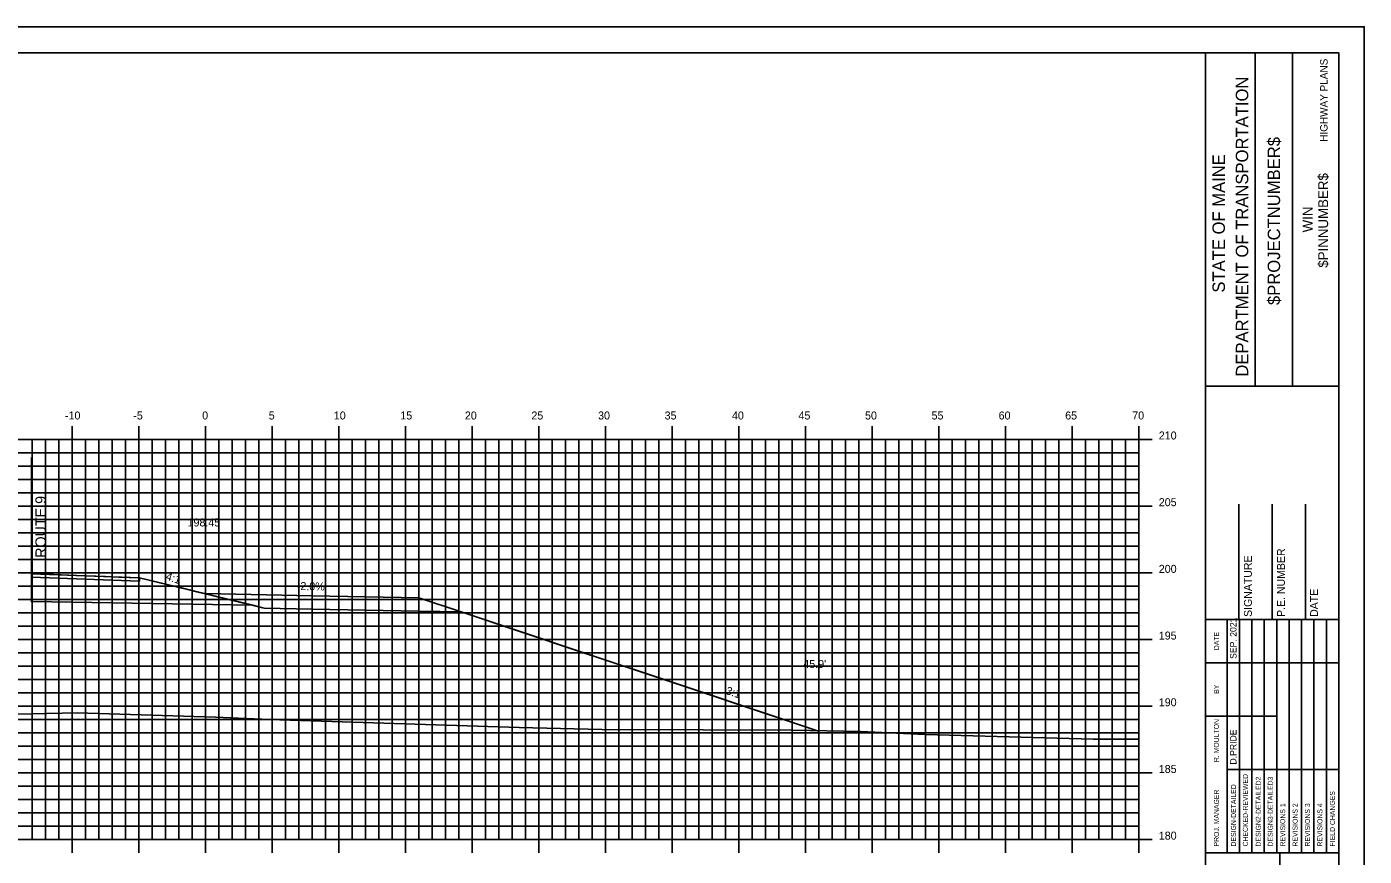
# Model space of a CAD drawing. Extents: x 1723296 to 1723468, y 459560 to 459670.
# Drawn here: x 1723365.8 to 1723466.1, y 459607.4 to 459669.6 of the extents above; entities that cross this region are included whole.
import ezdxf

# ---------------------------------------------------------------- set-up
doc = ezdxf.new("R2010")
doc.units = 0
for name, color, linetype in [('ANNOTATION', 7, 'Continuous'), ('BORDER', 7, 'Continuous'), ('D_Roadway_Centerline', 7, 'Continuous'), ('D_Roadway_Centerline_Text', 7, 'Continuous'), ('D_Roadway_Drive_Gravel', 7, 'Continuous'), ('D_Roadway_Edge_Shoulder', 7, 'Continuous'), ('D_Roadway_Edge_TW', 7, 'Continuous'), ('D_Roadway_Pavement', 7, 'Continuous'), ('D_Roadway_SlopeLines', 7, 'Continuous'), ('D_Roadway_SubGrade', 7, 'Continuous'), ('D_Text_Standard', 7, 'Continuous'), ('H_V ANNOTATION', 7, 'Continuous'), ('HIGHWAY_TITLE', 7, 'Continuous'), ('MAJOR', 7, 'Continuous'), ('MINOR', 7, 'Continuous'), ('PLOT BOUNDARY', 7, 'Continuous'), ('S_Roadway_Centerline', 7, 'Continuous')]:
    doc.layers.add(name, color=color, linetype=linetype)

msp = doc.modelspace()

# ---------------------------------------------------------------- linework, layer by layer
msp.add_lwpolyline([(1723379.2, 459627.06), (1723387.2, 459626.9), (1723395.2, 459626.74), (1723398.39, 459625.68), (1723407.19, 459622.75), (1723411.66, 459621.26), (1723416.09, 459619.78), (1723425.1, 459616.78), (1723425.12, 459616.77), (1723425.16, 459616.76), (1723425.17, 459616.75), (1723425.22, 459616.74)])
at = {"layer": 'BORDER'}
for p, q in [((1723454.2, 459562.61), (1723454.2, 459667.61)), ((1723457.93, 459642.61), (1723457.93, 459667.61)), ((1723460.73, 459642.61), (1723460.73, 459667.61)), ((1723454.2, 459642.61), (1723464.2, 459642.61)), ((1723456.7, 459625.12), (1723456.7, 459633.76)), ((1723459.2, 459625.12), (1723459.2, 459633.76)), ((1723461.7, 459625.12), (1723461.7, 459633.76)), ((1723454.2, 459625.12), (1723464.2, 459625.12)), ((1723454.2, 459607.62), (1723464.2, 459607.62)), ((1723459.79, 459572.62), (1723459.79, 459607.62))]:
    msp.add_line(p, q, dxfattribs=at)
msp.add_lwpolyline([(1723304.2, 459562.61), (1723464.2, 459562.61), (1723464.2, 459667.61), (1723304.2, 459667.61)], close=True, dxfattribs=at)
for points in [[(1723455.82, 459621.87), (1723455.82, 459625.12)], [(1723456.75, 459607.62), (1723456.75, 459625.12)], [(1723457.68, 459625.12), (1723457.68, 459607.62)], [(1723458.61, 459607.62), (1723458.61, 459625.12)], [(1723459.55, 459607.62), (1723459.55, 459625.12)], [(1723460.48, 459607.62), (1723460.48, 459625.12)], [(1723461.41, 459607.62), (1723461.41, 459625.12)], [(1723462.34, 459607.62), (1723462.34, 459625.12)], [(1723463.27, 459607.62), (1723463.27, 459625.12)], [(1723455.82, 459607.62), (1723455.82, 459624.41)], [(1723454.2, 459621.87), (1723464.2, 459621.87)], [(1723454.2, 459617.87), (1723455.82, 459617.87)], [(1723455.82, 459617.87), (1723459.55, 459617.87)], [(1723455.82, 459613.87), (1723464.2, 459613.87)]]:
    msp.add_lwpolyline(points, dxfattribs=at)
at = {"layer": 'D_Roadway_Centerline'}
msp.add_lwpolyline([(1723366.15, 459628.55), (1723366.89, 459628.52), (1723367.25, 459628.51), (1723369.52, 459628.42), (1723371.72, 459628.34), (1723372.72, 459628.3), (1723374.27, 459628.25), (1723376.51, 459627.7), (1723377.22, 459627.53), (1723378.56, 459627.2), (1723382.76, 459626.18), (1723383.5, 459626), (1723383.6, 459625.97)], dxfattribs=at)
at = {"layer": 'D_Roadway_Drive_Gravel'}
msp.add_lwpolyline([(1723379.2, 459627.05), (1723379.2, 459627.06), (1723387.2, 459626.9), (1723395.2, 459626.74), (1723398.39, 459625.68), (1723395.2, 459625.74), (1723387.2, 459625.9), (1723383.6, 459625.97)], dxfattribs=at)
at = {"layer": 'D_Roadway_Edge_Shoulder'}
msp.add_lwpolyline([(1723366.15, 459628.55), (1723374.27, 459628.25), (1723374.27, 459628), (1723366.15, 459628.3)], close=True, dxfattribs=at)
msp.add_lwpolyline([(1723366.15, 459628.55), (1723374.27, 459628.25), (1723374.27, 459628), (1723366.15, 459628.3)], close=True, dxfattribs=at)
at = {"layer": 'D_Roadway_Edge_TW'}
msp.add_line((1723366.15, 459628.55), (1723366.15, 459628.3), dxfattribs=at)
msp.add_line((1723366.15, 459628.55), (1723366.15, 459628.3), dxfattribs=at)
msp.add_line((1723366.15, 459628.55), (1723366.15, 459628.3), dxfattribs=at)
at = {"layer": 'D_Roadway_Pavement'}
msp.add_line((1723366.15, 459628.3), (1723366.15, 459627.88), dxfattribs=at)
msp.add_line((1723366.15, 459628.3), (1723366.15, 459627.88), dxfattribs=at)
msp.add_lwpolyline([(1723366.15, 459628.3), (1723366.15, 459627.88)], dxfattribs=at)
at = {"layer": 'D_Roadway_SlopeLines'}
for points in [[(1723374.27, 459628.25), (1723383.6, 459625.97)], [(1723374.27, 459628.25), (1723383.6, 459625.97)], [(1723374.27, 459628.25), (1723383.6, 459625.97)], [(1723374.27, 459628.25), (1723383.6, 459625.97)], [(1723374.27, 459628.25), (1723383.6, 459625.97)], [(1723374.27, 459628.25), (1723383.6, 459625.97)], [(1723374.27, 459628.25), (1723383.6, 459625.97)], [(1723379.2, 459627.06), (1723379.2, 459627.05)], [(1723395.2, 459626.74), (1723398.39, 459625.68), (1723425.1, 459616.78)]]:
    msp.add_lwpolyline(points, dxfattribs=at)
at = {"layer": 'D_Roadway_SubGrade'}
for p in [(1723366.15, 459637.25), (1723366.15, 459628.3)]:
    msp.add_line(p, (1723366.15, 459626.46), dxfattribs=at)
for points in [[(1723366.15, 459627.88), (1723366.15, 459628.3), (1723374.27, 459628), (1723374.27, 459628.25), (1723382.76, 459626.18), (1723366.15, 459626.46)], [(1723366.15, 459628.3), (1723374.27, 459628), (1723374.27, 459628.25), (1723382.76, 459626.18), (1723366.15, 459626.46)]]:
    msp.add_lwpolyline(points, close=True, dxfattribs=at)
for points in [[(1723366.15, 459628.3), (1723374.27, 459628), (1723374.27, 459628.25), (1723382.76, 459626.18), (1723366.15, 459626.46)], [(1723366.15, 459627.88), (1723366.15, 459628.3), (1723366.15, 459626.46)], [(1723366.15, 459628.3), (1723374.27, 459628), (1723374.27, 459628.25), (1723382.76, 459626.18), (1723366.15, 459626.46)]]:
    msp.add_lwpolyline(points, dxfattribs=at)
at = {"layer": 'MAJOR'}
for p, q in [((1723369.2, 459639.61), (1723369.2, 459638.61)), ((1723374.2, 459639.61), (1723374.2, 459638.61)), ((1723379.2, 459639.61), (1723379.2, 459638.61)), ((1723384.2, 459639.61), (1723384.2, 459638.61)), ((1723389.2, 459639.61), (1723389.2, 459638.61)), ((1723394.2, 459639.61), (1723394.2, 459638.61)), ((1723399.2, 459639.61), (1723399.2, 459638.61)), ((1723404.2, 459639.61), (1723404.2, 459638.61)), ((1723409.2, 459639.61), (1723409.2, 459638.61)), ((1723414.2, 459639.61), (1723414.2, 459638.61)), ((1723419.2, 459639.61), (1723419.2, 459638.61)), ((1723424.2, 459639.61), (1723424.2, 459638.61)), ((1723429.2, 459639.61), (1723429.2, 459638.61)), ((1723434.2, 459639.61), (1723434.2, 459638.61)), ((1723439.2, 459639.61), (1723439.2, 459638.61)), ((1723444.2, 459639.61), (1723444.2, 459638.61)), ((1723449.2, 459639.61), (1723449.2, 459638.61)), ((1723309.2, 459638.61), (1723449.2, 459638.61)), ((1723309.2, 459638.61), (1723449.2, 459638.61)), ((1723369.2, 459608.61), (1723369.2, 459638.61)), ((1723374.2, 459608.61), (1723374.2, 459638.61)), ((1723379.2, 459608.61), (1723379.2, 459638.61)), ((1723384.2, 459608.61), (1723384.2, 459638.61)), ((1723389.2, 459608.61), (1723389.2, 459638.61)), ((1723394.2, 459608.61), (1723394.2, 459638.61)), ((1723399.2, 459608.61), (1723399.2, 459638.61)), ((1723404.2, 459608.61), (1723404.2, 459638.61)), ((1723409.2, 459608.61), (1723409.2, 459638.61)), ((1723414.2, 459608.61), (1723414.2, 459638.61)), ((1723419.2, 459608.61), (1723419.2, 459638.61)), ((1723424.2, 459608.61), (1723424.2, 459638.61)), ((1723429.2, 459608.61), (1723429.2, 459638.61)), ((1723434.2, 459608.61), (1723434.2, 459638.61)), ((1723439.2, 459608.61), (1723439.2, 459638.61)), ((1723444.2, 459608.61), (1723444.2, 459638.61)), ((1723450.21, 459638.61), (1723448.2, 459638.61)), ((1723449.2, 459608.61), (1723449.2, 459638.61)), ((1723449.2, 459608.61), (1723449.2, 459638.61)), ((1723309.2, 459633.61), (1723449.2, 459633.61)), ((1723450.21, 459633.61), (1723448.2, 459633.61)), ((1723309.2, 459628.61), (1723449.2, 459628.61)), ((1723450.21, 459628.61), (1723448.2, 459628.61)), ((1723309.2, 459623.61), (1723449.2, 459623.61)), ((1723450.21, 459623.61), (1723448.2, 459623.61)), ((1723309.2, 459618.61), (1723449.2, 459618.61)), ((1723450.21, 459618.61), (1723448.2, 459618.61)), ((1723309.2, 459613.61), (1723449.2, 459613.61)), ((1723450.21, 459613.61), (1723448.2, 459613.61)), ((1723309.2, 459608.61), (1723449.2, 459608.61)), ((1723309.2, 459608.61), (1723449.2, 459608.61)), ((1723369.2, 459607.61), (1723369.2, 459608.61)), ((1723374.2, 459607.61), (1723374.2, 459608.61)), ((1723379.2, 459607.61), (1723379.2, 459608.61)), ((1723384.2, 459607.61), (1723384.2, 459608.61)), ((1723389.2, 459607.61), (1723389.2, 459608.61)), ((1723394.2, 459607.61), (1723394.2, 459608.61)), ((1723399.2, 459607.61), (1723399.2, 459608.61)), ((1723404.2, 459607.61), (1723404.2, 459608.61)), ((1723409.2, 459607.61), (1723409.2, 459608.61)), ((1723414.2, 459607.61), (1723414.2, 459608.61)), ((1723419.2, 459607.61), (1723419.2, 459608.61)), ((1723424.2, 459607.61), (1723424.2, 459608.61)), ((1723429.2, 459607.61), (1723429.2, 459608.61)), ((1723434.2, 459607.61), (1723434.2, 459608.61)), ((1723439.2, 459607.61), (1723439.2, 459608.61)), ((1723444.2, 459607.61), (1723444.2, 459608.61)), ((1723450.21, 459608.61), (1723448.2, 459608.61)), ((1723449.2, 459607.61), (1723449.2, 459608.61))]:
    msp.add_line(p, q, dxfattribs=at)
at = {"layer": 'MINOR'}
for p, q in [((1723366.2, 459608.61), (1723366.2, 459638.61)), ((1723367.2, 459608.61), (1723367.2, 459638.61)), ((1723368.2, 459608.61), (1723368.2, 459638.61)), ((1723370.2, 459608.61), (1723370.2, 459638.61)), ((1723371.2, 459608.61), (1723371.2, 459638.61)), ((1723372.2, 459608.61), (1723372.2, 459638.61)), ((1723373.2, 459608.61), (1723373.2, 459638.61)), ((1723375.2, 459608.61), (1723375.2, 459638.61)), ((1723376.2, 459608.61), (1723376.2, 459638.61)), ((1723377.2, 459608.61), (1723377.2, 459638.61)), ((1723378.2, 459608.61), (1723378.2, 459638.61)), ((1723380.2, 459608.61), (1723380.2, 459638.61)), ((1723381.2, 459608.61), (1723381.2, 459638.61)), ((1723382.2, 459608.61), (1723382.2, 459638.61)), ((1723383.2, 459608.61), (1723383.2, 459638.61)), ((1723385.2, 459608.61), (1723385.2, 459638.61)), ((1723386.2, 459608.61), (1723386.2, 459638.61)), ((1723387.2, 459608.61), (1723387.2, 459638.61)), ((1723388.2, 459608.61), (1723388.2, 459638.61)), ((1723390.2, 459608.61), (1723390.2, 459638.61)), ((1723391.2, 459608.61), (1723391.2, 459638.61)), ((1723392.2, 459608.61), (1723392.2, 459638.61)), ((1723393.2, 459608.61), (1723393.2, 459638.61)), ((1723395.2, 459608.61), (1723395.2, 459638.61)), ((1723396.2, 459608.61), (1723396.2, 459638.61)), ((1723397.2, 459608.61), (1723397.2, 459638.61)), ((1723398.2, 459608.61), (1723398.2, 459638.61)), ((1723400.2, 459608.61), (1723400.2, 459638.61)), ((1723401.2, 459608.61), (1723401.2, 459638.61)), ((1723402.2, 459608.61), (1723402.2, 459638.61)), ((1723403.2, 459608.61), (1723403.2, 459638.61)), ((1723405.2, 459608.61), (1723405.2, 459638.61)), ((1723406.2, 459608.61), (1723406.2, 459638.61)), ((1723407.2, 459608.61), (1723407.2, 459638.61)), ((1723408.2, 459608.61), (1723408.2, 459638.61)), ((1723410.2, 459608.61), (1723410.2, 459638.61)), ((1723411.2, 459608.61), (1723411.2, 459638.61)), ((1723412.2, 459608.61), (1723412.2, 459638.61)), ((1723413.2, 459608.61), (1723413.2, 459638.61)), ((1723415.2, 459608.61), (1723415.2, 459638.61)), ((1723416.2, 459608.61), (1723416.2, 459638.61)), ((1723417.2, 459608.61), (1723417.2, 459638.61)), ((1723418.2, 459608.61), (1723418.2, 459638.61)), ((1723420.2, 459608.61), (1723420.2, 459638.61)), ((1723421.2, 459608.61), (1723421.2, 459638.61)), ((1723422.2, 459608.61), (1723422.2, 459638.61)), ((1723423.2, 459608.61), (1723423.2, 459638.61)), ((1723425.2, 459608.61), (1723425.2, 459638.61)), ((1723426.2, 459608.61), (1723426.2, 459638.61)), ((1723427.2, 459608.61), (1723427.2, 459638.61)), ((1723428.2, 459608.61), (1723428.2, 459638.61)), ((1723430.2, 459608.61), (1723430.2, 459638.61)), ((1723431.2, 459608.61), (1723431.2, 459638.61)), ((1723432.2, 459608.61), (1723432.2, 459638.61)), ((1723433.2, 459608.61), (1723433.2, 459638.61)), ((1723435.2, 459608.61), (1723435.2, 459638.61)), ((1723436.2, 459608.61), (1723436.2, 459638.61)), ((1723437.2, 459608.61), (1723437.2, 459638.61)), ((1723438.2, 459608.61), (1723438.2, 459638.61)), ((1723440.2, 459608.61), (1723440.2, 459638.61)), ((1723441.2, 459608.61), (1723441.2, 459638.61)), ((1723442.2, 459608.61), (1723442.2, 459638.61)), ((1723443.2, 459608.61), (1723443.2, 459638.61)), ((1723445.2, 459608.61), (1723445.2, 459638.61)), ((1723446.2, 459608.61), (1723446.2, 459638.61)), ((1723447.2, 459608.61), (1723447.2, 459638.61)), ((1723448.2, 459608.61), (1723448.2, 459638.61)), ((1723309.2, 459637.61), (1723449.2, 459637.61)), ((1723449.2, 459637.61), (1723448.2, 459637.61)), ((1723309.2, 459636.61), (1723449.2, 459636.61)), ((1723449.2, 459636.61), (1723448.2, 459636.61)), ((1723309.2, 459635.61), (1723449.2, 459635.61)), ((1723449.2, 459635.61), (1723448.2, 459635.61)), ((1723309.2, 459634.61), (1723449.2, 459634.61)), ((1723449.2, 459634.61), (1723448.2, 459634.61)), ((1723309.2, 459632.61), (1723449.2, 459632.61)), ((1723449.2, 459632.61), (1723448.2, 459632.61)), ((1723309.2, 459631.61), (1723449.2, 459631.61)), ((1723449.2, 459631.61), (1723448.2, 459631.61)), ((1723309.2, 459630.61), (1723449.2, 459630.61)), ((1723449.2, 459630.61), (1723448.2, 459630.61)), ((1723309.2, 459629.61), (1723449.2, 459629.61)), ((1723449.2, 459629.61), (1723448.2, 459629.61)), ((1723309.2, 459627.61), (1723449.2, 459627.61)), ((1723449.2, 459627.61), (1723448.2, 459627.61)), ((1723309.2, 459626.61), (1723449.2, 459626.61)), ((1723449.2, 459626.61), (1723448.2, 459626.61)), ((1723309.2, 459625.61), (1723449.2, 459625.61)), ((1723449.2, 459625.61), (1723448.2, 459625.61)), ((1723309.2, 459624.61), (1723449.2, 459624.61)), ((1723449.2, 459624.61), (1723448.2, 459624.61)), ((1723309.2, 459622.61), (1723449.2, 459622.61)), ((1723449.2, 459622.61), (1723448.2, 459622.61)), ((1723309.2, 459621.61), (1723449.2, 459621.61)), ((1723449.2, 459621.61), (1723448.2, 459621.61)), ((1723309.2, 459620.61), (1723449.2, 459620.61)), ((1723449.2, 459620.61), (1723448.2, 459620.61)), ((1723309.2, 459619.61), (1723449.2, 459619.61)), ((1723449.2, 459619.61), (1723448.2, 459619.61)), ((1723309.2, 459617.61), (1723449.2, 459617.61)), ((1723449.2, 459617.61), (1723448.2, 459617.61)), ((1723309.2, 459616.61), (1723449.2, 459616.61)), ((1723449.2, 459616.61), (1723448.2, 459616.61)), ((1723309.2, 459615.61), (1723449.2, 459615.61)), ((1723449.2, 459615.61), (1723448.2, 459615.61)), ((1723309.2, 459614.61), (1723449.2, 459614.61)), ((1723449.2, 459614.61), (1723448.2, 459614.61)), ((1723309.2, 459612.61), (1723449.2, 459612.61)), ((1723449.2, 459612.61), (1723448.2, 459612.61)), ((1723309.2, 459611.61), (1723449.2, 459611.61)), ((1723449.2, 459611.61), (1723448.2, 459611.61)), ((1723309.2, 459610.61), (1723449.2, 459610.61)), ((1723449.2, 459610.61), (1723448.2, 459610.61)), ((1723309.2, 459609.61), (1723449.2, 459609.61)), ((1723449.2, 459609.61), (1723448.2, 459609.61))]:
    msp.add_line(p, q, dxfattribs=at)
at = {"layer": 'PLOT BOUNDARY'}
msp.add_lwpolyline([(1723296.11, 459559.55), (1723466.11, 459559.55), (1723466.11, 459669.55), (1723296.11, 459669.55)], close=True, dxfattribs=at)
at = {"layer": 'S_Roadway_Centerline'}
msp.add_lwpolyline([(1723309.2, 459619.22), (1723315.44, 459619.07), (1723323.59, 459619.13), (1723330.85, 459618.7), (1723334.23, 459618.54), (1723337.49, 459618.62), (1723347.09, 459618.82), (1723356.46, 459618.06), (1723359.35, 459617.9), (1723369.59, 459618.12), (1723379.96, 459617.79), (1723384.01, 459617.61), (1723402.73, 459617.01), (1723408.94, 459616.86), (1723416.53, 459616.84), (1723423.26, 459616.81), (1723428.32, 459616.72), (1723433.19, 459616.5), (1723445.78, 459616.14), (1723449.2, 459616.14)], dxfattribs=at)

# ---------------------------------------------------------------- texts
at = {"layer": 'ANNOTATION'}
for s, height, rotation, p in [('ROUTE 9', 0.8, 90, (1723367.25, 459629.74)), ('4:1', 0.6, 341.5651, (1723376.18, 459628.11)), ('-2.0%', 0.6, 358.8542, (1723386.05, 459627.33)), ('3:1', 0.6, 341.5651, (1723418.18, 459619.54))]:
    msp.add_text(s, height=height, rotation=rotation, dxfattribs=at).set_placement(p)
at = {"layer": 'BORDER'}
for s, height, p in [('DEPARTMENT OF TRANSPORTATION', 0.9318, (1723457.41, 459643.32)), ('$PROJECTNUMBER$', 0.9318, (1723459.8, 459648.69)), ('STATE OF MAINE', 0.9318, (1723455.66, 459649.62)), ('$PINNUMBER$', 0.7453, (1723463.4, 459651.49)), ('WIN', 0.745, (1723462.24, 459654.14)), ('SIGNATURE', 0.591, (1723457.68, 459625.31)), ('P.E. NUMBER', 0.5906, (1723460.16, 459625.31)), ('DATE', 0.591, (1723462.64, 459625.31)), ('SEP. 2021', 0.485, (1723456.53, 459622.16)), ('DATE', 0.371, (1723455.21, 459622.82)), ('BY', 0.371, (1723455.21, 459619.55)), ('R. MOULTON', 0.373, (1723455.21, 459614.42)), ('D.PRIDE', 0.485, (1723456.53, 459614.24)), ('DESIGN-DETAILED', 0.3727, (1723456.49, 459608.1)), ('CHECKED-REVIEWED', 0.3727, (1723457.38, 459608.1)), ('DESIGN2-DETAILED2', 0.3727, (1723458.35, 459608.1)), ('DESIGN3-DETAILED3', 0.3727, (1723459.25, 459608.1)), ('PROJ. MANAGER', 0.3727, (1723455.21, 459608.1)), ('FIELD CHANGES', 0.3727, (1723463.91, 459608.1)), ('REVISIONS 1', 0.3727, (1723460.18, 459608.1)), ('REVISIONS 2', 0.3727, (1723461.11, 459608.1)), ('REVISIONS 3', 0.3727, (1723462.04, 459608.1)), ('REVISIONS 4', 0.3727, (1723462.97, 459608.1))]:
    msp.add_text(s, height=height, rotation=90, dxfattribs=at).set_placement(p)
at = {"layer": 'D_Roadway_Centerline_Text'}
msp.add_text('198.45', height=0.6, dxfattribs=at).set_placement((1723377.86, 459632.09))
at = {"layer": 'D_Text_Standard'}
msp.add_text("45.9'", height=0.6, dxfattribs=at).set_placement((1723424.04, 459621.48))
at = {"layer": 'H_V ANNOTATION'}
for s, p in [('-10', (1723368.67, 459640.11)), ('-5', (1723373.79, 459640.11)), ('0', (1723378.96, 459640.11)), ('5', (1723383.95, 459640.11)), ('10', (1723388.83, 459640.11)), ('15', (1723393.82, 459640.11)), ('20', (1723398.66, 459640.11)), ('25', (1723403.65, 459640.11)), ('30', (1723408.65, 459640.11)), ('35', (1723413.64, 459640.11)), ('40', (1723418.69, 459640.11)), ('45', (1723423.68, 459640.11)), ('50', (1723428.67, 459640.11)), ('55', (1723433.66, 459640.11)), ('60', (1723438.69, 459640.11)), ('65', (1723443.68, 459640.11)), ('70', (1723448.71, 459640.11)), ('210', (1723450.7, 459638.61)), ('205', (1723450.7, 459633.61)), ('200', (1723450.7, 459628.61)), ('195', (1723450.7, 459623.61)), ('190', (1723450.7, 459618.61)), ('185', (1723450.7, 459613.61)), ('180', (1723450.7, 459608.61))]:
    msp.add_text(s, height=0.6, dxfattribs=at).set_placement(p)
at = {"layer": 'HIGHWAY_TITLE'}
msp.add_text('HIGHWAY PLANS', height=0.559, rotation=90, dxfattribs=at).set_placement((1723463.36, 459660.93))

doc.saveas('drawing.dxf')
